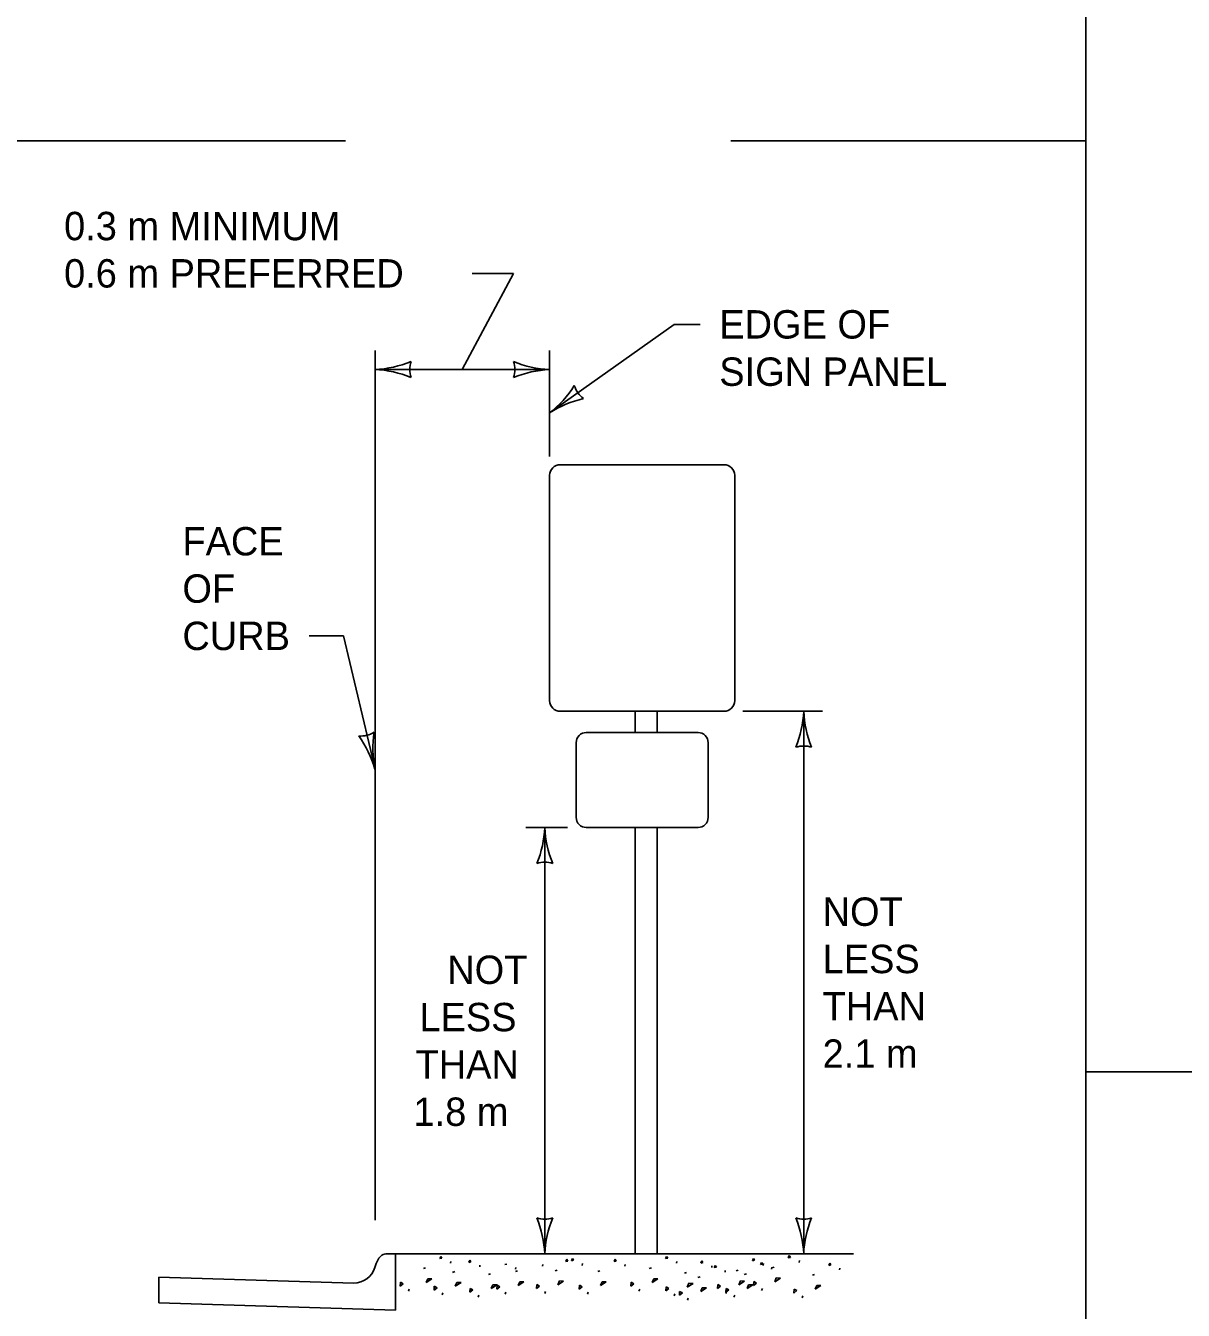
# Model space of a CAD drawing. Extents: x 49991.4 to 50021, y 49987.6 to 50011.4.
# Drawn here: x 50005.827 to 50008.273, y 49993.569 to 49996.284 of the extents above; entities that cross this region are included whole.
import ezdxf

# ---------------------------------------------------------------- set-up
doc = ezdxf.new("R2010")
doc.units = 0
for name, color, linetype in [('Level 1', 7, 'Continuous'), ('Level 2', 7, 'Continuous'), ('Level 3', 7, 'Continuous')]:
    doc.layers.add(name, color=color, linetype=linetype)

msp = doc.modelspace()

# ---------------------------------------------------------------- linework, layer by layer
at = {"layer": 'Level 1'}
for p, q in [((50006.9565, 49995.3563), (50007.3026, 49995.3563)), ((50006.934, 49994.8576), (50006.934, 49995.3338)), ((50007.3251, 49995.3338), (50007.3251, 49994.8576)), ((50007.3026, 49994.8351), (50006.9565, 49994.8351)), ((50007.1151, 49994.7902), (50007.1151, 49994.8351)), ((50007.1613, 49994.7902), (50007.1613, 49994.8351)), ((50006.9901, 49994.611), (50006.9901, 49994.7687)), ((50007.0116, 49994.7902), (50007.2476, 49994.7902)), ((50007.2691, 49994.7687), (50007.2691, 49994.611)), ((50007.2476, 49994.5895), (50007.0116, 49994.5895)), ((50007.1151, 49993.6882), (50007.1151, 49994.5895)), ((50007.1613, 49993.6882), (50007.1613, 49994.5895)), ((50006.6082, 49993.6882), (50006.5912, 49993.6882)), ((50006.6082, 49993.6882), (50007.5762, 49993.6882)), ((50006.6082, 49993.5697), (50006.6082, 49993.6882)), ((50006.7019, 49993.6784), (50006.7039, 49993.6831)), ((50006.7039, 49993.6831), (50006.7063, 49993.6795)), ((50007.1792, 49993.6784), (50007.1813, 49993.6831)), ((50007.1813, 49993.6831), (50007.1837, 49993.6795)), ((50007.4384, 49993.68), (50007.4404, 49993.6847)), ((50007.4429, 49993.681), (50007.4384, 49993.68)), ((50007.4404, 49993.6847), (50007.4429, 49993.681)), ((50006.6719, 49993.6588), (50006.6673, 49993.6573)), ((50006.7063, 49993.6795), (50006.7019, 49993.6784)), ((50006.7248, 49993.6688), (50006.7253, 49993.6724)), ((50006.7635, 49993.6704), (50006.7655, 49993.6751)), ((50006.7679, 49993.6715), (50006.7635, 49993.6704)), ((50006.7655, 49993.6751), (50006.7679, 49993.6715)), ((50006.7864, 49993.6608), (50006.7869, 49993.6644)), ((50006.8439, 49993.6667), (50006.8394, 49993.6656)), ((50006.8623, 49993.6561), (50006.8628, 49993.6597)), ((50006.9192, 49993.6625), (50006.9197, 49993.6661)), ((50006.9501, 49993.6541), (50006.9455, 49993.6525)), ((50006.9681, 49993.6721), (50006.9701, 49993.6768)), ((50006.9726, 49993.6732), (50006.9681, 49993.6721)), ((50006.9701, 49993.6768), (50006.9726, 49993.6732)), ((50006.9801, 49993.6736), (50006.9821, 49993.6784)), ((50006.9846, 49993.6747), (50006.9801, 49993.6736)), ((50006.9821, 49993.6784), (50006.9846, 49993.6747)), ((50007.003, 49993.6641), (50007.0035, 49993.6677)), ((50007.0702, 49993.6721), (50007.0722, 49993.6768)), ((50007.0747, 49993.6732), (50007.0702, 49993.6721)), ((50007.0722, 49993.6768), (50007.0747, 49993.6732)), ((50007.0931, 49993.6625), (50007.0936, 49993.6661)), ((50007.1493, 49993.6588), (50007.1446, 49993.6573)), ((50007.1837, 49993.6795), (50007.1792, 49993.6784)), ((50007.2021, 49993.6688), (50007.2026, 49993.6724)), ((50007.2536, 49993.6688), (50007.2556, 49993.6735)), ((50007.258, 49993.6699), (50007.2536, 49993.6688)), ((50007.2556, 49993.6735), (50007.258, 49993.6699)), ((50007.2765, 49993.6592), (50007.277, 49993.6629)), ((50007.2819, 49993.6593), (50007.284, 49993.6641)), ((50007.2864, 49993.6604), (50007.2819, 49993.6593)), ((50007.284, 49993.6641), (50007.2864, 49993.6604)), ((50007.3326, 49993.6541), (50007.328, 49993.6525)), ((50007.3626, 49993.6736), (50007.3646, 49993.6784)), ((50007.3671, 49993.6747), (50007.3626, 49993.6736)), ((50007.3646, 49993.6784), (50007.3671, 49993.6747)), ((50007.3799, 49993.6656), (50007.382, 49993.6704)), ((50007.3844, 49993.6667), (50007.3799, 49993.6656)), ((50007.382, 49993.6704), (50007.3844, 49993.6667)), ((50007.3855, 49993.6641), (50007.386, 49993.6677)), ((50007.4028, 49993.6561), (50007.4033, 49993.6597)), ((50007.4084, 49993.6604), (50007.4038, 49993.6588)), ((50007.4613, 49993.6704), (50007.4618, 49993.674)), ((50007.5238, 49993.6641), (50007.5258, 49993.6688)), ((50007.5283, 49993.6652), (50007.5238, 49993.6641)), ((50007.5258, 49993.6688), (50007.5283, 49993.6652)), ((50007.5467, 49993.6545), (50007.5472, 49993.6581)), ((50006.5199, 49993.6265), (50006.1083, 49993.6388)), ((50006.1083, 49993.6388), (50006.1083, 49993.5846)), ((50006.6185, 49993.6199), (50006.619, 49993.6282)), ((50006.619, 49993.6282), (50006.6248, 49993.6249)), ((50006.6765, 49993.6358), (50006.6732, 49993.6279)), ((50006.6732, 49993.6279), (50006.6854, 49993.6356)), ((50006.6854, 49993.6356), (50006.6765, 49993.6358)), ((50006.7335, 49993.6508), (50006.7289, 49993.6493)), ((50006.7381, 49993.6278), (50006.7348, 49993.6199)), ((50006.7348, 49993.6199), (50006.747, 49993.6276)), ((50006.747, 49993.6276), (50006.7381, 49993.6278)), ((50006.8094, 49993.6461), (50006.8048, 49993.6445)), ((50006.8663, 49993.6525), (50006.8617, 49993.651)), ((50006.8709, 49993.6295), (50006.8676, 49993.6216)), ((50006.8676, 49993.6216), (50006.8798, 49993.6293)), ((50006.8798, 49993.6293), (50006.8709, 49993.6295)), ((50006.9547, 49993.6311), (50006.9514, 49993.6232)), ((50006.9514, 49993.6232), (50006.9636, 49993.6308)), ((50006.9636, 49993.6308), (50006.9547, 49993.6311)), ((50007.0402, 49993.6525), (50007.0356, 49993.651)), ((50007.0448, 49993.6295), (50007.0416, 49993.6216)), ((50007.0416, 49993.6216), (50007.0537, 49993.6293)), ((50007.0537, 49993.6293), (50007.0448, 49993.6295)), ((50007.1056, 49993.6199), (50007.1061, 49993.6282)), ((50007.1061, 49993.6282), (50007.1119, 49993.6249)), ((50007.1539, 49993.6358), (50007.1506, 49993.6279)), ((50007.1506, 49993.6279), (50007.1627, 49993.6356)), ((50007.1627, 49993.6356), (50007.1539, 49993.6358)), ((50007.2236, 49993.6493), (50007.219, 49993.6477)), ((50007.252, 49993.6398), (50007.2474, 49993.6382)), ((50007.3049, 49993.6498), (50007.3053, 49993.6534)), ((50007.3372, 49993.6311), (50007.334, 49993.6232)), ((50007.334, 49993.6232), (50007.3461, 49993.6308)), ((50007.3461, 49993.6308), (50007.3372, 49993.6311)), ((50007.35, 49993.6461), (50007.3454, 49993.6445)), ((50007.3648, 49993.6215), (50007.3653, 49993.6297)), ((50007.3711, 49993.6265), (50007.3648, 49993.6215)), ((50007.3653, 49993.6297), (50007.3711, 49993.6265)), ((50007.413, 49993.6374), (50007.4098, 49993.6295)), ((50007.4098, 49993.6295), (50007.4219, 49993.6371)), ((50007.4219, 49993.6371), (50007.413, 49993.6374)), ((50007.4938, 49993.6445), (50007.4892, 49993.643)), ((50006.6248, 49993.6249), (50006.6185, 49993.6199)), ((50006.6373, 49993.6137), (50006.6358, 49993.6095)), ((50006.6898, 49993.6119), (50006.6903, 49993.6202)), ((50006.6962, 49993.6169), (50006.6898, 49993.6119)), ((50006.6903, 49993.6202), (50006.6962, 49993.6169)), ((50006.7086, 49993.6057), (50006.7071, 49993.6015)), ((50006.7658, 49993.6072), (50006.7663, 49993.6154)), ((50006.7721, 49993.6122), (50006.7658, 49993.6072)), ((50006.7663, 49993.6154), (50006.7721, 49993.6122)), ((50006.7846, 49993.601), (50006.783, 49993.5968)), ((50006.814, 49993.6231), (50006.8108, 49993.6152)), ((50006.8108, 49993.6152), (50006.8229, 49993.6228)), ((50006.8229, 49993.6228), (50006.814, 49993.6231)), ((50006.8226, 49993.6136), (50006.8231, 49993.6219)), ((50006.829, 49993.6186), (50006.8226, 49993.6136)), ((50006.8231, 49993.6219), (50006.829, 49993.6186)), ((50006.8414, 49993.6074), (50006.8399, 49993.6032)), ((50006.9065, 49993.6152), (50006.9069, 49993.6234)), ((50006.9128, 49993.6202), (50006.9065, 49993.6152)), ((50006.9069, 49993.6234), (50006.9128, 49993.6202)), ((50006.9252, 49993.609), (50006.9237, 49993.6048)), ((50006.9966, 49993.6136), (50006.997, 49993.6219)), ((50007.0029, 49993.6186), (50006.9966, 49993.6136)), ((50006.997, 49993.6219), (50007.0029, 49993.6186)), ((50007.0154, 49993.6074), (50007.0138, 49993.6032)), ((50007.1119, 49993.6249), (50007.1056, 49993.6199)), ((50007.1244, 49993.6137), (50007.1228, 49993.6095)), ((50007.1799, 49993.6103), (50007.1804, 49993.6186)), ((50007.1862, 49993.6153), (50007.1799, 49993.6103)), ((50007.1804, 49993.6186), (50007.1862, 49993.6153)), ((50007.1987, 49993.6042), (50007.1972, 49993.5999)), ((50007.2083, 49993.6009), (50007.2088, 49993.6091)), ((50007.2146, 49993.6059), (50007.2083, 49993.6009)), ((50007.2088, 49993.6091), (50007.2146, 49993.6059)), ((50007.2282, 49993.6262), (50007.2249, 49993.6183)), ((50007.2249, 49993.6183), (50007.2371, 49993.626)), ((50007.2371, 49993.626), (50007.2282, 49993.6262)), ((50007.2566, 49993.6168), (50007.2533, 49993.6089)), ((50007.2533, 49993.6089), (50007.2654, 49993.6165)), ((50007.2654, 49993.6165), (50007.2566, 49993.6168)), ((50007.289, 49993.6152), (50007.2895, 49993.6234)), ((50007.2953, 49993.6202), (50007.289, 49993.6152)), ((50007.2895, 49993.6234), (50007.2953, 49993.6202)), ((50007.3078, 49993.609), (50007.3062, 49993.6048)), ((50007.3063, 49993.6072), (50007.3068, 49993.6154)), ((50007.3126, 49993.6122), (50007.3063, 49993.6072)), ((50007.3068, 49993.6154), (50007.3126, 49993.6122)), ((50007.3251, 49993.601), (50007.3235, 49993.5968)), ((50007.3546, 49993.6231), (50007.3513, 49993.6152)), ((50007.3513, 49993.6152), (50007.3634, 49993.6228)), ((50007.3634, 49993.6228), (50007.3546, 49993.6231)), ((50007.3836, 49993.6153), (50007.382, 49993.6111)), ((50007.4501, 49993.6056), (50007.4506, 49993.6139)), ((50007.4565, 49993.6106), (50007.4501, 49993.6056)), ((50007.4506, 49993.6139), (50007.4565, 49993.6106)), ((50007.4689, 49993.5994), (50007.4674, 49993.5952)), ((50007.4984, 49993.6215), (50007.4951, 49993.6136)), ((50007.4951, 49993.6136), (50007.5073, 49993.6213)), ((50007.5073, 49993.6213), (50007.4984, 49993.6215)), ((50006.1083, 49993.5846), (50006.6082, 49993.5697)), ((50007.2271, 49993.5947), (50007.2255, 49993.5904))]:
    msp.add_line(p, q, dxfattribs=at)
for centre, radius, start, end in [((50006.9565, 49995.3338), 0.0225, 90, 180), ((50007.3026, 49995.3338), 0.0225, 0, 90), ((50006.9565, 49994.8576), 0.0225, 180, 270), ((50007.3026, 49994.8576), 0.0225, 270, 0), ((50007.0116, 49994.7687), 0.0215, 90, 180), ((50007.2476, 49994.7687), 0.0215, 0, 90), ((50007.0116, 49994.611), 0.0215, 180, 270), ((50007.2476, 49994.611), 0.0215, 270, 0), ((50006.5896, 49993.6689), 0.0194, 85.3754, 156.6889), ((50006.5195, 49993.6742), 0.0477, 270.4937, 342.4535), ((50006.616, 49993.6489), 0.0521, 148.469, 167.8949)]:
    msp.add_arc(centre, radius, start, end, dxfattribs=at)
at = {"layer": 'Level 3'}
for p, q in [((50008.0668, 49998.9992), (50008.0668, 49994.0732)), ((50005.0025, 49996.0407), (50006.5025, 49996.0407)), ((50007.3168, 49996.0407), (50008.0668, 49996.0407)), ((50006.7495, 49995.5574), (50006.8577, 49995.7607)), ((50006.8577, 49995.7607), (50006.7702, 49995.7607)), ((50006.934, 49995.4656), (50007.1971, 49995.6529)), ((50007.1971, 49995.6529), (50007.2525, 49995.6529)), ((50006.5651, 49993.7598), (50006.5651, 49995.5974)), ((50006.934, 49995.3738), (50006.934, 49995.5974)), ((50006.5651, 49995.5574), (50006.934, 49995.5574)), ((50006.4263, 49994.9945), (50006.4983, 49994.9945)), ((50006.4983, 49994.9945), (50006.5651, 49994.713)), ((50007.3426, 49994.8351), (50007.5109, 49994.8351)), ((50007.4709, 49993.6882), (50007.4709, 49994.8351)), ((50006.8838, 49994.5895), (50006.9716, 49994.5895)), ((50006.9238, 49993.6882), (50006.9238, 49994.5895)), ((50008.0668, 49994.0732), (50016.7501, 49994.0732)), ((50008.0668, 49994.0732), (50008.0668, 49987.7988))]:
    msp.add_line(p, q, dxfattribs=at)
for centre, radius, start, end in [((50006.5536, 49995.7901), 0.233, 272.8273, 292.0772), ((50006.5559, 49995.3353), 0.2223, 67.456, 87.6395), ((50006.6933, 49995.5574), 0.0548, 162.1388, 197.8612), ((50006.9432, 49995.7795), 0.2223, 247.456, 267.6395), ((50006.8058, 49995.5574), 0.0548, 342.1388, 17.8612), ((50006.9455, 49995.3247), 0.233, 92.8273, 112.0772), ((50006.7897, 49995.6485), 0.233, 308.2742, 327.5241), ((50007.0385, 49995.54), 0.0548, 197.5858, 233.3081), ((50007.0554, 49995.2793), 0.2223, 102.9029, 123.0865), ((50007.2488, 49994.8443), 0.2223, 337.456, 357.6395), ((50007.7036, 49994.8466), 0.233, 182.8273, 202.0772), ((50006.5347, 49994.8376), 0.0548, 265.8498, 301.5721), ((50006.3417, 49994.6467), 0.233, 16.5382, 35.7881), ((50006.783, 49994.7568), 0.2223, 171.1669, 191.3505), ((50007.4709, 49994.7069), 0.0548, 72.1388, 107.8612), ((50006.7017, 49994.5987), 0.2223, 337.456, 357.6395), ((50007.1565, 49994.601), 0.233, 182.8273, 202.0772), ((50006.9238, 49994.4613), 0.0548, 72.1388, 107.8612), ((50006.9238, 49993.8164), 0.0548, 252.1388, 287.8612), ((50006.6911, 49993.6767), 0.233, 2.8273, 22.0772), ((50007.1459, 49993.679), 0.2223, 157.456, 177.6395), ((50007.4709, 49993.8164), 0.0548, 252.1388, 287.8612), ((50007.2382, 49993.6767), 0.233, 2.8273, 22.0772), ((50007.693, 49993.679), 0.2223, 157.456, 177.6395)]:
    msp.add_arc(centre, radius, start, end, dxfattribs=at)

# ---------------------------------------------------------------- texts
at = {"layer": 'Level 2'}
for s, p in [('0.3 m MINIMUM', (50005.9081, 49995.8307)), ('0.6 m PREFERRED', (50005.9081, 49995.7307)), ('EDGE OF', (50007.2925, 49995.6229)), ('SIGN PANEL', (50007.2925, 49995.5229)), ('FACE', (50006.1581, 49995.1645)), ('OF', (50006.1581, 49995.0645)), ('CURB', (50006.1581, 49994.9645)), ('NOT', (50007.5109, 49994.3816)), ('LESS', (50007.5109, 49994.2816)), ('NOT', (50006.7177, 49994.2588)), ('THAN', (50007.5109, 49994.1816)), ('LESS', (50006.6589, 49994.1588)), ('2.1 m', (50007.5109, 49994.0816)), ('THAN', (50006.6507, 49994.0588)), ('1.8 m', (50006.6464, 49993.9588))]:
    msp.add_text(s, height=0.06, dxfattribs=at).set_placement(p)

doc.saveas('drawing.dxf')
